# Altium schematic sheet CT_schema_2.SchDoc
size 403 x 258 mm
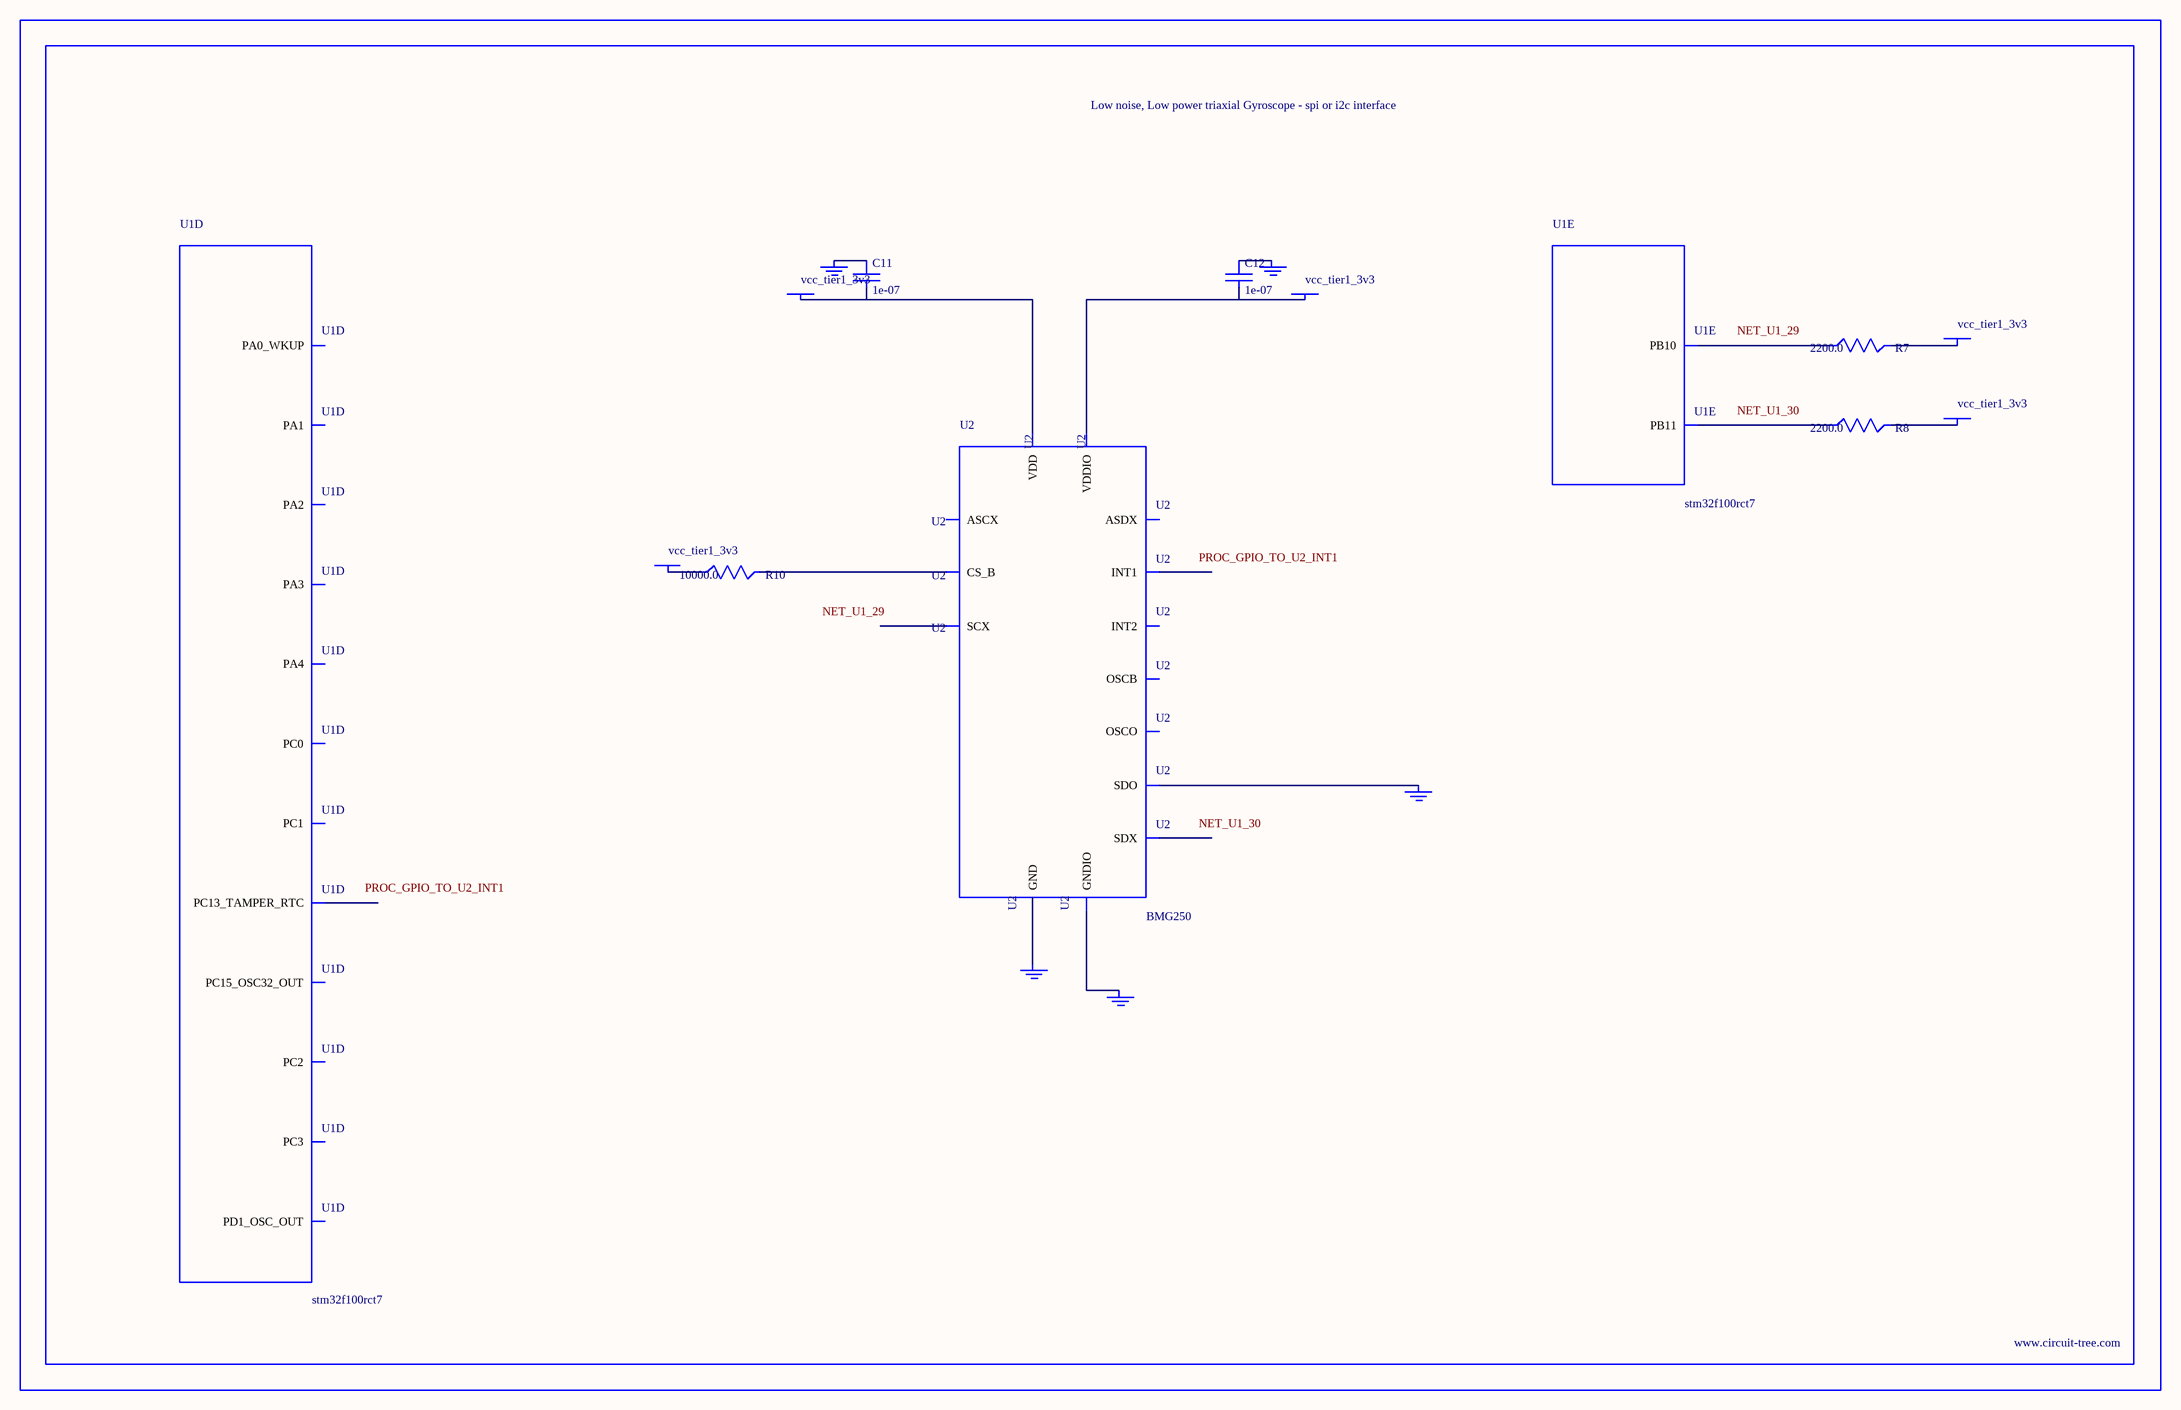
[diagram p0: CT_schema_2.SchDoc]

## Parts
BORDER1  (no value)
C11  1e-07  [C0402]
C12  1e-07  [C0402]
GND_INSTANCE_1_0  (no value)
GND_INSTANCE_1_1  (no value)
GND_INSTANCE_1_2  (no value)
GND_INSTANCE_1_3  (no value)
GND_INSTANCE_1_4  (no value)
POWER_INSTANCE_1_0  vcc_tier1_3v3
POWER_INSTANCE_1_1  vcc_tier1_3v3
POWER_INSTANCE_1_2  vcc_tier1_3v3
POWER_INSTANCE_1_3  vcc_tier1_3v3
POWER_INSTANCE_1_4  vcc_tier1_3v3
R7  2200.0  [R0603]
R8  2200.0  [R0603]
R10  10000.0  [R0603]
U1  stm32f100rct7  [LQFP64]  (parts D,E of 6)
U2  BMG250  [LGA-14]

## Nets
NetC11_1: C11.1 GND_INSTANCE_1_3.0(GND)
NetC11_2: C11.2 POWER_INSTANCE_1_1.0(PWR) U2.8(VDD)
NetC12_1: C12.1 GND_INSTANCE_1_1.0(GND)
NetC12_2: C12.2 POWER_INSTANCE_1_0.0(PWR) U2.5(VDDIO)
NetGND_INSTANCE_1_0_0: GND_INSTANCE_1_0.0(GND) U2.1(SDO)
NetGND_INSTANCE_1_2_0: GND_INSTANCE_1_2.0(GND) U2.6(GNDIO)
NetGND_INSTANCE_1_4_0: GND_INSTANCE_1_4.0(GND) U2.7(GND)
NetPOWER_INSTANCE_1_2_0: POWER_INSTANCE_1_2.0(PWR) R10.1
NetPOWER_INSTANCE_1_3_0: POWER_INSTANCE_1_3.0(PWR) R7.2
NetPOWER_INSTANCE_1_4_0: POWER_INSTANCE_1_4.0(PWR) R8.2
NetR7_1: R7.1 U1.29(PB10)
NetR8_1: R8.1 U1.30(PB11)
NetR10_2: R10.2 U2.12(CS_B)

Not connected (* = marked no-connect by the designer): U1 2(PC13_TAMPER_RTC) 4(PC15_OSC32_OUT) 6(PD1_OSC_OUT) 8(PC0) 9(PC1) 10(PC2) 11(PC3) 14(PA0_WKUP) 15(PA1) 16(PA2) 17(PA3) 20(PA4); U2 2(ASDX) 3(ASCX) 4(INT1) 9(INT2) 10(OSCB) 11(OSCO) 13(SCX) 14(SDX)

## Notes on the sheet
- Labels drawn without touching a wire or pin: NET_U1_29, NET_U1_30, PROC_GPIO_TO_U2_INT1

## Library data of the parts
BORDER1 = BORDER_PAGE1
C11 C12 = C0402C104K3RACTU
GND_INSTANCE_1_0-GND_INSTANCE_1_4 = GND
POWER_INSTANCE_1_0-POWER_INSTANCE_1_4 = PWR
R7 R8 = RC0603JR-072K2L
R10 = RC0603JR-0710KL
